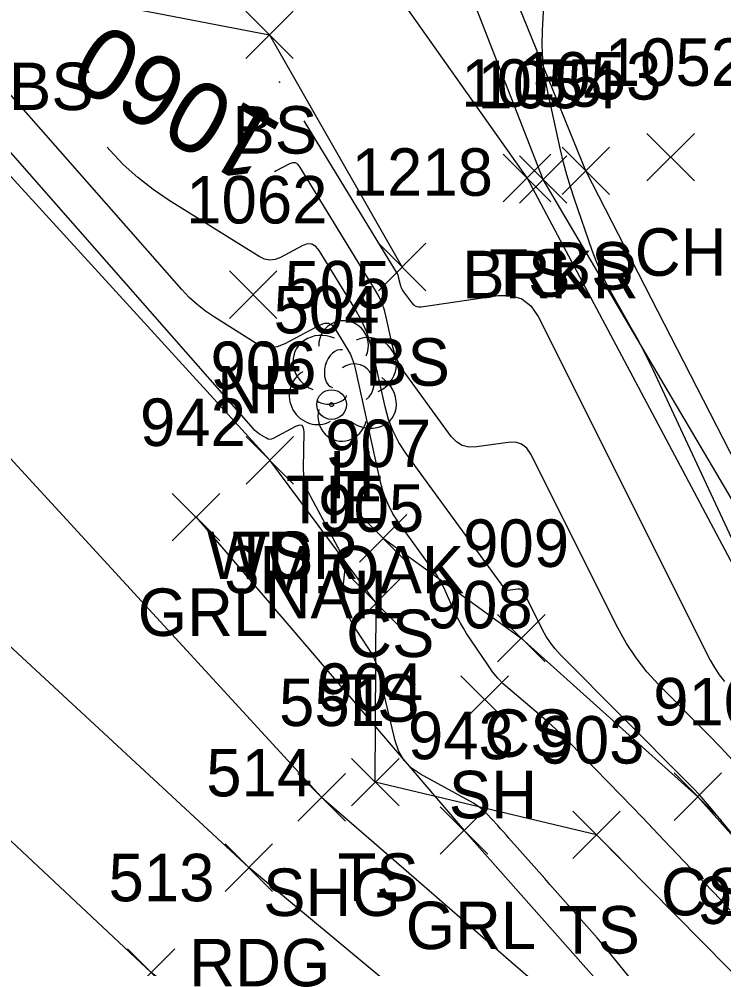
# Model space of a CAD drawing. Extents: x 1592612 to 1596497, y 111838 to 113741.
# Drawn here: x 1592810.29 to 1592839.94, y 113483.39 to 113523.36 of the extents above; entities that cross this region are included whole.
import ezdxf

# ---------------------------------------------------------------- set-up
doc = ezdxf.new("R2010")
doc.units = 0
for name, color, linetype in [('C_A', 7, 'Continuous'), ('C_C', 7, 'Continuous'), ('C_I', 7, 'Continuous'), ('CBP', 7, 'Continuous'), ('L_A', 7, 'Continuous'), ('L_C', 7, 'Continuous'), ('L_I', 7, 'Continuous'), ('L_TIC', 7, 'Continuous'), ('LAWA', 7, 'Continuous'), ('LAWE', 7, 'Continuous'), ('LELB', 7, 'Continuous'), ('LSOGCMA', 7, 'Continuous'), ('LSOGCMA_T', 7, 'Continuous'), ('LSOGCMI', 7, 'Continuous'), ('LTD', 7, 'Continuous'), ('P_A', 7, 'Continuous'), ('P_I', 7, 'Continuous'), ('P_TIC', 7, 'Continuous'), ('PEU', 7, 'Continuous'), ('PRC', 7, 'Continuous'), ('PSU', 7, 'Continuous'), ('R_A', 7, 'Continuous'), ('R_I', 7, 'Continuous'), ('R_TIC', 7, 'Continuous'), ('RGR', 7, 'Continuous')]:
    doc.layers.add(name, color=color, linetype=linetype)

msp = doc.modelspace()

# ---------------------------------------------------------------- linework, layer by layer
at = {"layer": 'CBP'}
for radius in [0.625, 0.0833]:
    msp.add_circle((1592823.454, 113507.121), radius, dxfattribs=at)
at = {"layer": 'L_TIC'}
for points in [[(1592819.841, 113521.69), (1592821.841, 113523.69)], [(1592821.841, 113521.69), (1592819.841, 113523.69)], [(1592836.737, 113516.544), (1592838.737, 113518.544)], [(1592838.737, 113516.544), (1592836.737, 113518.544)], [(1592833.164, 113515.964), (1592835.164, 113517.964)], [(1592835.164, 113515.964), (1592833.164, 113517.964)], [(1592830.688, 113515.664), (1592832.688, 113517.664)], [(1592832.688, 113515.664), (1592830.688, 113517.664)], [(1592831.37, 113515.6), (1592833.37, 113517.6)], [(1592833.37, 113515.6), (1592831.37, 113517.6)], [(1592825.429, 113511.914), (1592827.429, 113513.914)], [(1592827.429, 113511.914), (1592825.429, 113513.914)], [(1592819.153, 113510.749), (1592821.153, 113512.749)], [(1592821.153, 113510.749), (1592819.153, 113512.749)], [(1592819.851, 113503.774), (1592821.851, 113505.774)], [(1592821.851, 113503.774), (1592819.851, 113505.774)], [(1592819.851, 113503.774), (1592821.851, 113505.774)], [(1592821.851, 113503.774), (1592819.851, 113505.774)], [(1592824.629, 113500.489), (1592826.629, 113502.489)], [(1592826.629, 113500.489), (1592824.629, 113502.489)], [(1592824.334, 113497.762), (1592826.334, 113499.762)], [(1592826.334, 113497.762), (1592824.334, 113499.762)], [(1592830.446, 113496.284), (1592832.446, 113498.284)], [(1592832.446, 113496.284), (1592830.446, 113498.284)], [(1592828.904, 113493.697), (1592830.904, 113495.697)], [(1592830.904, 113493.697), (1592828.904, 113495.697)], [(1592824.295, 113490.22), (1592826.295, 113492.22)], [(1592826.295, 113490.22), (1592824.295, 113492.22)], [(1592837.885, 113489.608), (1592839.885, 113491.608)], [(1592839.885, 113489.608), (1592837.885, 113491.608)], [(1592833.613, 113488.001), (1592835.613, 113490.001)], [(1592835.613, 113488.001), (1592833.613, 113490.001)]]:
    msp.add_lwpolyline(points, dxfattribs=at)
at = {"layer": 'LAWA'}
msp.add_lwpolyline([(1592820.851, 113504.774), (1592798.01, 113529.796), (1592767.974, 113554.756), (1592744.7, 113575.871), (1592731.754, 113590.187), (1592719.52, 113602.847), (1592702.926, 113618.445), (1592691.78, 113628.612), (1592676.133, 113644.708)], dxfattribs=at)
at = {"layer": 'LAWE'}
msp.add_lwpolyline([(1592867.645, 113460.38), (1592859.409, 113477.515), (1592844.793, 113495.549), (1592832.37, 113516.6), (1592826.928, 113530.545), (1592818.762, 113547.936), (1592807.597, 113581.108), (1592797.669, 113603.177), (1592787.513, 113626.88), (1592776.477, 113646.362), (1592766.38, 113665.342), (1592748.736, 113682.085), (1592730.356, 113695.945)], dxfattribs=at)
at = {"layer": 'LELB'}
for points in [[(1592869.098, 113460.398), (1592860.441, 113478.115), (1592844.631, 113496.556), (1592834.165, 113516.964), (1592828.396, 113531.171), (1592823.559, 113549.918), (1592808.456, 113581.723), (1592799.527, 113603.061), (1592789.48, 113627.849), (1592777.21, 113647.427), (1592766.461, 113666.146), (1592749.422, 113683.288), (1592730.933, 113697.021)], [(1592856.492, 113476.867), (1592843.193, 113495.045), (1592831.688, 113516.664), (1592823.204, 113528.692), (1592814.853, 113545.459), (1592806.797, 113580.845), (1592796.452, 113601.854), (1592785.293, 113626.354), (1592775.723, 113645.654), (1592766.309, 113664.453), (1592745.043, 113679.184), (1592727.847, 113694.217)], [(1592701.588, 113659.774), (1592726.097, 113635.895), (1592737.453, 113625.119), (1592757.272, 113620.552), (1592765.525, 113604.487), (1592785.217, 113593.362), (1592785.143, 113579.955), (1592783.097, 113567.939), (1592785.828, 113560.008), (1592797.4, 113544.62), (1592809.213, 113533.643), (1592811.425, 113524.524), (1592820.841, 113522.69), (1592826.429, 113512.914)], [(1592852.772, 113465.837), (1592843.246, 113475.946), (1592841.284, 113482.249), (1592834.613, 113489.001), (1592825.295, 113491.22), (1592825.335, 113498.762), (1592820.851, 113504.775)], [(1592825.629, 113501.489), (1592831.446, 113497.285), (1592838.885, 113490.608), (1592846.044, 113482.577), (1592850.995, 113476.269), (1592857.832, 113468.308), (1592859.25, 113463.159)]]:
    msp.add_lwpolyline(points, dxfattribs=at)
at = {"layer": 'LSOGCMA'}
msp.add_lwpolyline([(1592840.362, 113492.133), (1592839.855, 113492.679), (1592839.336, 113493.213), (1592837.234, 113495.325), (1592836.732, 113495.871), (1592836.278, 113496.451), (1592835.873, 113497.065), (1592835.515, 113497.714), (1592831.851, 113505.027), (1592831.678, 113505.283), (1592831.459, 113505.453), (1592831.195, 113505.535), (1592830.886, 113505.53), (1592829.557, 113505.337), (1592829.241, 113505.329), (1592828.959, 113505.4), (1592828.711, 113505.552), (1592828.497, 113505.783), (1592826.517, 113508.5), (1592826.35, 113508.755), (1592826.212, 113509.023), (1592826.103, 113509.304), (1592826.023, 113509.599), (1592825.759, 113510.801), (1592825.681, 113511.097), (1592825.58, 113511.384), (1592825.454, 113511.661), (1592825.306, 113511.928), (1592822.124, 113517.134), (1592822.035, 113517.243), (1592821.931, 113517.299), (1592821.813, 113517.303), (1592821.681, 113517.255), (1592821.123, 113516.959), (1592821.049, 113516.929)], dxfattribs=at)
at = {"layer": 'LSOGCMI'}
for points in [[(1592843.148, 113495.407), (1592836.997, 113508.58), (1592836.793, 113509.006), (1592836.582, 113509.427), (1592836.362, 113509.844), (1592836.134, 113510.257), (1592835.205, 113511.902), (1592834.983, 113512.317), (1592834.78, 113512.741), (1592834.596, 113513.174), (1592834.432, 113513.616), (1592833.683, 113515.777), (1592833.514, 113516.288), (1592833.361, 113516.803), (1592833.223, 113517.323), (1592833.099, 113517.847), (1592832.533, 113520.425), (1592832.421, 113521.031), (1592832.351, 113521.641), (1592832.322, 113522.255), (1592832.334, 113522.871), (1592832.819, 113531.889)], [(1592836.957, 113481.825), (1592835.06, 113484.16), (1592834.849, 113484.416), (1592834.635, 113484.67), (1592834.419, 113484.921), (1592834.199, 113485.17), (1592833.314, 113486.161), (1592833.094, 113486.409), (1592832.873, 113486.657), (1592832.653, 113486.905), (1592832.434, 113487.155), (1592830.928, 113488.866), (1592830.811, 113488.998), (1592830.693, 113489.129), (1592830.575, 113489.259), (1592830.455, 113489.388), (1592829.976, 113489.904), (1592829.852, 113490.028), (1592829.719, 113490.14), (1592829.578, 113490.241), (1592829.428, 113490.332), (1592827.199, 113491.554), (1592826.815, 113491.815), (1592826.509, 113492.136), (1592826.281, 113492.517), (1592826.131, 113492.957), (1592825.444, 113495.871), (1592825.373, 113496.126), (1592825.28, 113496.371), (1592825.165, 113496.608), (1592825.029, 113496.835), (1592824.327, 113497.905), (1592824.247, 113498.041), (1592824.182, 113498.183), (1592824.133, 113498.331), (1592824.098, 113498.485), (1592823.983, 113499.166), (1592823.966, 113499.297), (1592823.957, 113499.428), (1592823.958, 113499.559), (1592823.967, 113499.691), (1592824.024, 113500.218), (1592824.028, 113500.348), (1592824.014, 113500.475), (1592823.98, 113500.597), (1592823.927, 113500.716), (1592822.575, 113503.229), (1592822.442, 113503.519), (1592822.348, 113503.819), (1592822.293, 113504.128), (1592822.278, 113504.447), (1592822.299, 113505.977), (1592822.279, 113506.145), (1592822.213, 113506.237), (1592822.1, 113506.254), (1592821.942, 113506.195), (1592820.999, 113505.694), (1592820.925, 113505.665), (1592820.852, 113505.657), (1592820.78, 113505.67), (1592820.708, 113505.704), (1592820.423, 113505.881), (1592820.354, 113505.928), (1592820.288, 113505.98), (1592820.227, 113506.036), (1592820.17, 113506.097), (1592800.29, 113528.724)], [(1592821.23, 113520.721), (1592821.239, 113520.721), (1592821.277, 113520.7), (1592821.287, 113520.688)], [(1592840.237, 113485.83), (1592839.862, 113486.247), (1592839.478, 113486.657), (1592837.455, 113488.783), (1592837.004, 113489.256), (1592836.55, 113489.728), (1592836.096, 113490.199), (1592835.64, 113490.668), (1592833.466, 113492.899), (1592833.18, 113493.186), (1592832.888, 113493.465), (1592832.588, 113493.737), (1592832.282, 113494.002), (1592830.962, 113495.117), (1592830.703, 113495.352), (1592830.462, 113495.604), (1592830.239, 113495.871), (1592830.035, 113496.155), (1592829.144, 113497.487), (1592829.008, 113497.701), (1592828.88, 113497.919), (1592828.762, 113498.143), (1592828.653, 113498.371), (1592828.234, 113499.296), (1592828.123, 113499.523), (1592828.002, 113499.745), (1592827.869, 113499.959), (1592827.725, 113500.168), (1592826.302, 113502.121), (1592826.038, 113502.525), (1592825.82, 113502.949), (1592825.647, 113503.395), (1592825.52, 113503.86), (1592824.483, 113508.585), (1592824.422, 113508.816), (1592824.343, 113509.039), (1592824.246, 113509.255), (1592824.13, 113509.463), (1592823.629, 113510.282), (1592823.493, 113510.448), (1592823.335, 113510.533), (1592823.156, 113510.54), (1592822.955, 113510.467), (1592821.481, 113509.683), (1592821.166, 113509.56), (1592820.855, 113509.526), (1592820.546, 113509.581), (1592820.241, 113509.726), (1592818.522, 113510.797), (1592818.145, 113511.052), (1592817.789, 113511.331), (1592817.455, 113511.637), (1592817.143, 113511.967), (1592809.679, 113520.463)], [(1592822.284, 113519.068), (1592826.179, 113512.694), (1592826.212, 113512.635), (1592826.24, 113512.573), (1592826.262, 113512.509), (1592826.28, 113512.443), (1592826.338, 113512.176), (1592826.356, 113512.11), (1592826.381, 113512.048), (1592826.411, 113511.988), (1592826.448, 113511.931), (1592826.825, 113511.414), (1592826.907, 113511.325), (1592827.003, 113511.267), (1592827.112, 113511.239), (1592827.233, 113511.243), (1592830.465, 113511.713), (1592831.007, 113511.721), (1592831.469, 113511.577), (1592831.852, 113511.28), (1592832.155, 113510.831), (1592839.404, 113496.362), (1592839.581, 113496.042), (1592839.781, 113495.739), (1592840.005, 113495.452)], [(1592840.44, 113488.908), (1592839.458, 113490.098), (1592839.209, 113490.392), (1592838.953, 113490.681), (1592838.691, 113490.963), (1592838.422, 113491.239), (1592833.087, 113496.6), (1592832.87, 113496.837), (1592832.673, 113497.089), (1592832.497, 113497.355), (1592832.341, 113497.637), (1592831.547, 113499.222), (1592831.504, 113499.286), (1592831.449, 113499.328), (1592831.383, 113499.349), (1592831.306, 113499.348), (1592830.973, 113499.299), (1592830.894, 113499.297), (1592830.824, 113499.315), (1592830.762, 113499.353), (1592830.708, 113499.411), (1592826.586, 113505.068), (1592826.289, 113505.522), (1592826.044, 113505.999), (1592825.85, 113506.499), (1592825.707, 113507.022), (1592825.238, 113509.159), (1592825.1, 113509.685), (1592824.919, 113510.194), (1592824.697, 113510.687), (1592824.433, 113511.162), (1592822.938, 113513.607), (1592822.792, 113513.785), (1592822.622, 113513.877), (1592822.43, 113513.884), (1592822.213, 113513.805), (1592821.302, 113513.321), (1592821.076, 113513.232), (1592820.851, 113513.207), (1592820.629, 113513.247), (1592820.409, 113513.352), (1592816.62, 113515.713), (1592815.935, 113516.175), (1592815.29, 113516.683), (1592814.683, 113517.237), (1592814.116, 113517.838), (1592814.004, 113517.966)]]:
    msp.add_lwpolyline(points, dxfattribs=at)
at = {"layer": 'LTD'}
msp.add_line((1592823.912, 113508.171), (1592823.912, 113508.171), dxfattribs=at)
msp.add_line((1592823.912, 113508.171), (1592823.912, 113508.171), dxfattribs=at)
msp.add_arc((1592823.959, 113509.605), 1.047, 335.5272, 180.9563, dxfattribs=at)
for centre, major_axis, ratio, start_param, end_param in [((1592823.12, 113508.838), (1.21, -0.512), 0.895232, 1.570796, 4.712389), ((1592824.953, 113508.755), (-1.141, -0.483), 0.949671, 1.570796, 4.712389), ((1592823.703, 113508.63), (-0.208, -0.792), 0.645439, 3.141593, 6.283185), ((1592824.412, 113508.005), (-0.5, 0.667), 0.989748, 3.141593, 6.283185), ((1592822.829, 113507.463), (0.584, -1.042), 0.959034, 3.141593, 6.283185), ((1592824.912, 113507.338), (-1.09, 0.792), 0.841452, 1.570796, 4.712389), ((1592823.454, 113507.421), (-0.625, -0.083), 0.423636, 0, 3.141593), ((1592823.912, 113506.671), (0.265, 1.061), 0.942809, 1.570796, 4.712389)]:
    msp.add_ellipse(centre, major_axis=major_axis, ratio=ratio, start_param=start_param, end_param=end_param, dxfattribs=at)
at = {"layer": 'P_TIC'}
for points in [[(1592822.037, 113489.583), (1592824.037, 113491.583)], [(1592824.037, 113489.583), (1592822.037, 113491.583)], [(1592818.972, 113486.621), (1592820.972, 113488.621)], [(1592820.972, 113486.621), (1592818.972, 113488.621)], [(1592814.857, 113482.202), (1592816.857, 113484.202)], [(1592816.857, 113482.202), (1592814.857, 113484.202)]]:
    msp.add_lwpolyline(points, dxfattribs=at)
at = {"layer": 'PEU'}
msp.add_lwpolyline([(1592852.273, 113463.849), (1592836.279, 113474.056), (1592819.972, 113487.621), (1592800.662, 113505.499), (1592780.779, 113527.086), (1592759.62, 113549.571), (1592738.37, 113572.943), (1592716.192, 113596.277), (1592693.964, 113619.189), (1592672.676, 113639.672)], dxfattribs=at)
at = {"layer": 'PRC'}
msp.add_lwpolyline([(1592851.008, 113460.149), (1592833.097, 113469.523), (1592815.857, 113483.202), (1592796.573, 113501.275), (1592777.295, 113523.934), (1592756.259, 113546.33), (1592734.615, 113569.346), (1592712.839, 113593.061), (1592690.495, 113615.302), (1592669.477, 113636.459)], dxfattribs=at)
at = {"layer": 'PSU'}
msp.add_lwpolyline([(1592770.049, 113548.457), (1592775.263, 113542.835), (1592780.478, 113537.214), (1592785.693, 113531.593), (1592790.602, 113526.158), (1592795.512, 113520.723), (1592800.422, 113515.288), (1592805.331, 113509.853), (1592809.758, 113505.035), (1592814.184, 113500.218), (1592818.611, 113495.4), (1592823.037, 113490.583), (1592826.914, 113487.218), (1592830.791, 113483.853), (1592834.668, 113480.488), (1592838.545, 113477.123), (1592845.634, 113471.053), (1592852.707, 113464.996)], dxfattribs=at)
at = {"layer": 'R_TIC'}
for points in [[(1592816.747, 113501.377), (1592818.747, 113503.377)], [(1592818.747, 113501.377), (1592816.747, 113503.377)], [(1592828.033, 113488.186), (1592830.033, 113490.186)], [(1592830.033, 113488.186), (1592828.033, 113490.186)]]:
    msp.add_lwpolyline(points, dxfattribs=at)
at = {"layer": 'RGR'}
msp.add_lwpolyline([(1592817.747, 113502.377), (1592829.033, 113489.186), (1592839.839, 113476.992), (1592847.811, 113468.949), (1592852.564, 113465.029)], dxfattribs=at)
msp.add_lwpolyline([(1592817.747, 113502.377), (1592829.033, 113489.186), (1592839.839, 113476.992), (1592847.811, 113468.949), (1592852.564, 113465.029)], dxfattribs=at)

# ---------------------------------------------------------------- texts
at = {"layer": 'C_A'}
msp.add_text('TIE', height=2, dxfattribs=at).set_placement((1592821.533, 113502.121))
at = {"layer": 'C_C'}
msp.add_text('NAIL', height=2, dxfattribs=at).set_placement((1592820.635, 113498.121))
at = {"layer": 'C_I'}
msp.add_text('504', height=2, dxfattribs=at).set_placement((1592821.013, 113510.121))
at = {"layer": 'L_A'}
for s, p in [('BS', (1592809.866, 113519.523)), ('BS', (1592819.282, 113517.69)), ('CH', (1592836.226, 113512.544)), ('BS', (1592832.605, 113511.964)), ('BRKR', (1592828.96, 113511.6)), ('TS', (1592830.097, 113511.664)), ('BS', (1592824.87, 113507.914)), ('NF', (1592818.633, 113506.749)), ('H', (1592823.345, 113503.171)), ('TS', (1592819.261, 113499.774)), ('WDR', (1592818.213, 113499.774)), ('CS', (1592824.07, 113496.489)), ('TS', (1592823.744, 113493.762)), ('CS', (1592829.887, 113492.284)), ('SH', (1592828.393, 113489.697)), ('TS', (1592823.705, 113486.22)), ('CS', (1592837.326, 113485.608)), ('TS', (1592833.023, 113484.001))]:
    msp.add_text(s, height=2, dxfattribs=at).set_placement(p)
at = {"layer": 'L_C'}
msp.add_text('3M.OAK', height=2, dxfattribs=at).set_placement((1592818.935, 113499.171))
at = {"layer": 'L_I'}
for s, p in [('1052', (1592834.966, 113520.544)), ('1053', (1592831.393, 113519.964)), ('1055', (1592828.916, 113519.664)), ('1054', (1592829.598, 113519.6)), ('1218', (1592824.303, 113515.914)), ('1062', (1592817.334, 113514.749)), ('505', (1592821.471, 113511.171)), ('906', (1592818.355, 113507.774)), ('906', (1592818.355, 113507.774)), ('907', (1592823.188, 113504.489)), ('905', (1592822.894, 113501.762)), ('909', (1592828.997, 113500.284)), ('908', (1592827.463, 113497.697)), ('904', (1592822.854, 113494.22)), ('910', (1592837.003, 113493.608)), ('903', (1592832.172, 113492.001)), ('902', (1592838.843, 113485.249))]:
    msp.add_text(s, height=2, dxfattribs=at).set_placement(p)
at = {"layer": 'LSOGCMA_T'}
msp.add_text('1060', height=3, rotation=149.9941, dxfattribs=at).set_placement((1592821.495, 113518.836))
at = {"layer": 'P_A'}
for s, p in [('SHG', (1592820.572, 113485.583)), ('RDG', (1592817.46, 113482.621))]:
    msp.add_text(s, height=2, dxfattribs=at).set_placement(p)
at = {"layer": 'P_I'}
for s, p in [('551', (1592821.242, 113493.583)), ('514', (1592818.176, 113490.621)), ('513', (1592814.061, 113486.202))]:
    msp.add_text(s, height=2, dxfattribs=at).set_placement(p)
at = {"layer": 'R_A'}
for p in [(1592815.29, 113497.377), (1592826.576, 113484.186)]:
    msp.add_text('GRL', height=2, dxfattribs=at).set_placement(p)
at = {"layer": 'R_I'}
for s, p in [('942', (1592815.385, 113505.377)), ('943', (1592826.671, 113492.186))]:
    msp.add_text(s, height=2, dxfattribs=at).set_placement(p)

doc.saveas('drawing.dxf')
